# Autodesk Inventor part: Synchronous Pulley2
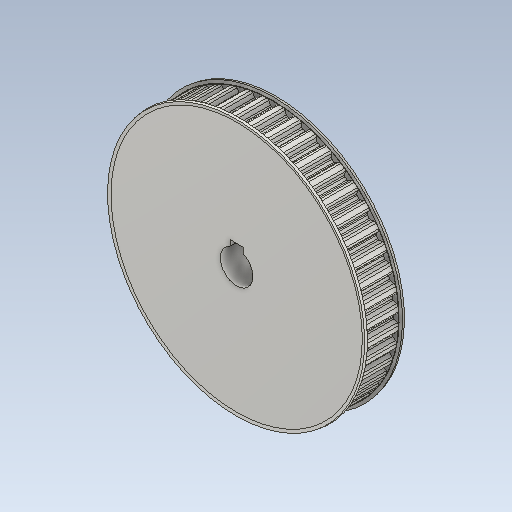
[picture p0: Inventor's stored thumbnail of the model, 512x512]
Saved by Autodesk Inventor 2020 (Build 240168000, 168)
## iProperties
CustomPartVersion: 1
Created: 2019-09
Part Number: Synchronous Pulley2
Material: Steel
Document SubType Name: Modeling
Designer: user
Density: 7.85 g/cm^3
Appearance: Steel
Mass: 417.005 g
Surface Area: 146.312 cm^2
Volume: 53.1217 cm^3
Author: user
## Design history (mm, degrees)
sketch "Pulley Sketch"
  geometry: L1 (-1.418, 38.528)-(-0.66, 36.903); L2 (-0.66, 36.903)-(0.66, 36.903); L3 (0.66, 36.903)-(1.418, 38.528); L4 (0, 0)-(0, 38.554); C1 r 38.808 at (0, 0); A1 r 38.554 centre (0, 0) between (-1.418, 38.528) and (1.418, 38.528); 2 further points
  constraints: 8 end point, 3 coincident, 3 point on circle, 2 centre point, 1 horizontal, 1 midpoint, 1 point on line, 1 vertical, 1 vertical alignment, 3 other
  dimensions: "d0" = 77.61668 diameter of C1 (computed from da_pb, da_z); "d1" = 0.254 radial gap between concentric circles of C1 A1 (= da_a); "d2" = 1.651 dimension on A1 (= da_hg); "d3" = 50 deg angle of L3 L1 (= 2 x da_fi); "d4" = 1.3208 distance of L1.end L2.end (= da_bw)
extrude "Base Body" new body sketch "Pulley Sketch" stored distance "d5" = 10.414 (= da_bf); taper "d6" = 0 deg
extrude "Tooth" cut sketch "Pulley Sketch" extent not by distance; stored distance "d7" = 10.414 (= da_bf); taper "d8" = 0 deg
fillet "Tooth Fillet" dims "d9" = 0.4064 (= da_rb), "d10" = 0.635 (= da_rt)
feature "Left flange"
feature "Right flange"
sketch "Sketch2"
  geometry: L1 (-2.03, 6.33)-(2.03, 6.33); L2 (2.03, 6.33)-(2.03, 4.569); L3 (-2.03, 4.569)-(-2.03, 6.33); A1 r 5 centre (0, 0) between (-2.03, 4.569) and (2.03, 4.569); 2 further points
  constraints: 6 end point, 2 point on circle, 1 centre point, 1 coincident, 1 horizontal, 1 midpoint, 1 parallel, 1 perpendicular, 1 vertical alignment
  dimensions: "d17" = 10 diameter of A1
extrude "Extrusion3" cut sketch "Sketch2" extent not by distance; stored distance "d18" = 0; taper "d19" = 0 deg
body "Solid1"
pattern_circular "Teeth" dims angle "d12" = 360 deg
other parameters: "da_pb" = 5.08 [user parameter; used in 1 equation term], "da_fi" = 25 deg [user parameter; used in 1 equation term], "da_hg" = 1.651 [user parameter; used in 1 equation term], "da_bw" = 1.3208 [user parameter; used in 1 equation term], "da_rb" = 0.4064 [user parameter; used in 1 equation term], "da_rt" = 0.635 [user parameter; used in 1 equation term], "da_a" = 0.254 [user parameter; used in 3 equation terms], "da_bf" = 10.414 [user parameter; used in 2 equation terms], "d15" = 0, "da_wf" = 0.7366 [user parameter; used in 2 equation terms], "da_hf" = 1.016 [user parameter; used in 2 equation terms], "d16" = 0
